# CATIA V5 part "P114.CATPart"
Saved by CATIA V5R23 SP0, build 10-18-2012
Part number: P114
Definition: couvercle de serrage plateau
Description: couvercle de serrage plateau
Bounding box of the stored display mesh (mm): x -23.957 to 23.957, y -24 to 24, z 0 to 10
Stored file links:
  C:\wamp\www\COURS\CONCEPTION GMP1\TITRE 02-SEMESTRE 2\03-TP7-PRESSE MECANIQUE\eleve\P114.CATPart
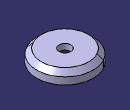
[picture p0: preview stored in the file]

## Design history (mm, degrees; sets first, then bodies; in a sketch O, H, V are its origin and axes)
Body1 (main body)
  Sketch1 on yz-plane, origin (0, 0, 0), H (0, 1, 0), V (0, 0, 1)
    point P1 (-24, 0)
    line L1 (-24, 0) -> (-24, 10)
    line L2 (-24, 10) -> (0, 10)
    line L3 (0, 10) -> (0, 5)
    line L4 (0, 5) -> (-21, 5)
    line L5 (-21, 5) -> (-21, 0)
    point P6 (-21, 0)
    line L6 (-21, 0) -> (-24, 0)
    distance L2 L4 = 5
    length L6 = 3
    distance L1 V = 24
    length L1 = 10
    coincidence: P1 H, P6 H, L3 V
    vertical: L1 V, L3 V, L5 V
    horizontal: L2 H, L4 H, L6 H
  Shaft1: profile Sketch1, axis Sketch1.V, angle 360
  Chamfer1: length 4, angle 45, on edge [face of Shaft1 | face of Shaft1]
  Sketch2 on face of Shaft1, origin (0, 0, 10), H (1, 0, 0), V (0, 1, 0)
    point P1 (0, 0)
  Hole1: placed by Sketch2, at (0, 0, 10) direction (0, 0, -1), diameter 10, through (limit type 3)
